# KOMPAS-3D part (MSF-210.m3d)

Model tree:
1. Ось X
2. Ось Y
3. Ось Z
4. Начало координат  (labels: Операция без истории:1)

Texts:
  Линия-выноска #1
  Линия-выноска #2
  Линия-выноска #3
  Отклонения формы и база
  Марка координационной оси
  Марка/позиционное обозначение с линией-выноской
  Марка/позиционное обозначение на линии
  Марка/позиционное обозначение без линии-выноски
